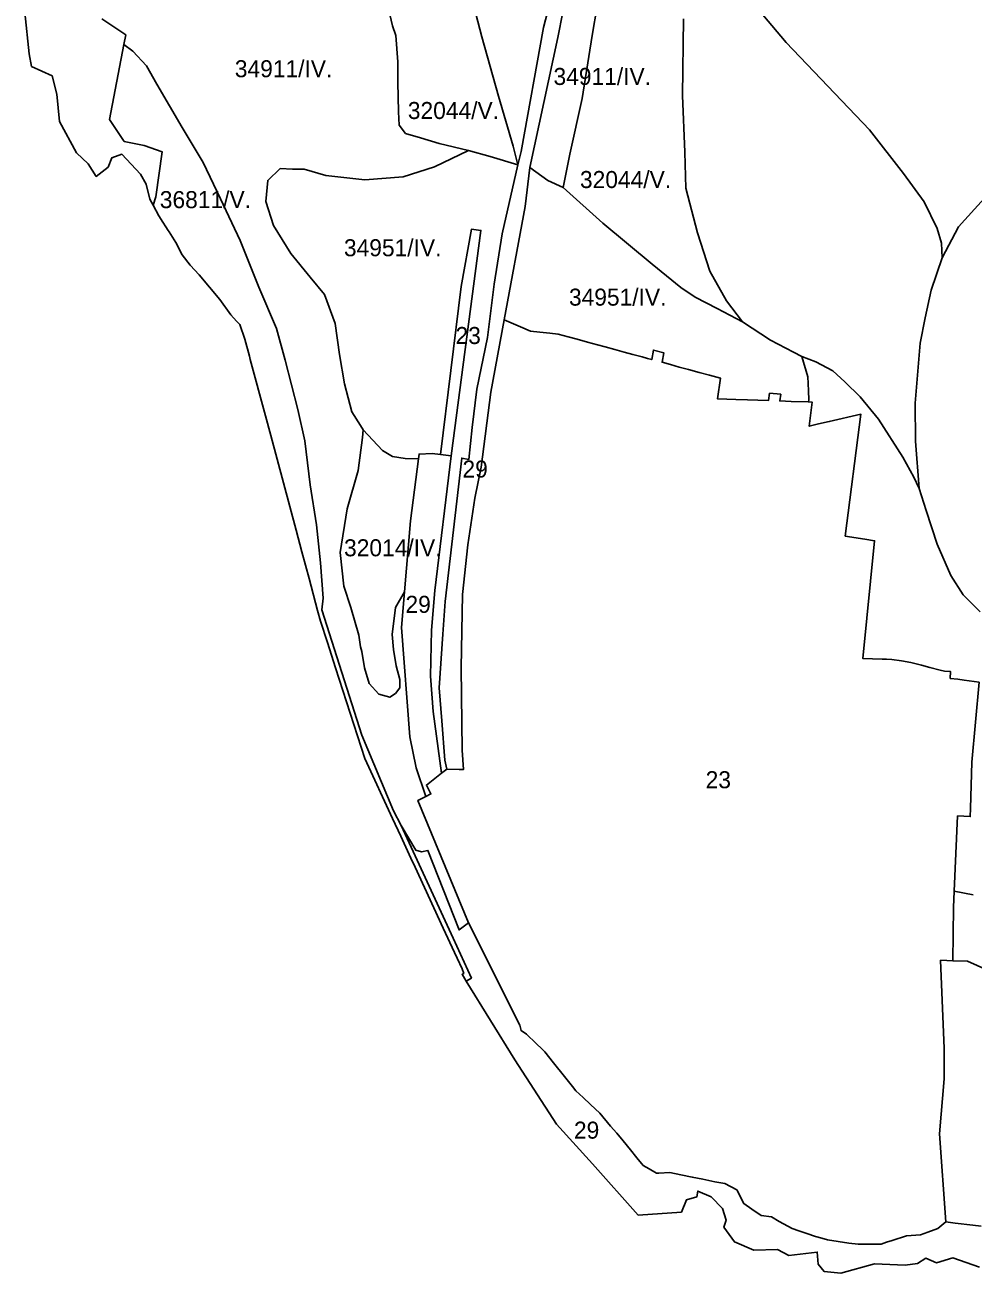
# Model space of a CAD drawing. Extents: x -521621 to -516761, y -1190184 to -1184927.
# Drawn here: x -520918 to -520083, y -1189812 to -1188713 of the extents above; entities that cross this region are included whole.
import ezdxf

# ---------------------------------------------------------------- set-up
doc = ezdxf.new("R2010")
doc.units = 0
doc.layers.add('BPEJ_s', color=7, linetype='Continuous')

msp = doc.modelspace()

# ---------------------------------------------------------------- linework, layer by layer
at = {"layer": 'BPEJ_s'}
for points in [[(-520473.2, -1188838.7), (-520448.5, -1188724), (-520435.4, -1188657), (-520429.1, -1188628.7), (-520418.3, -1188620.7), (-520409.7, -1188617.4), (-520401.2, -1188621.1), (-520400, -1188634.9), (-520404.1, -1188656.5), (-520413.8, -1188696.4), (-520418.3, -1188722.4), (-520427.2, -1188777.8), (-520437.8, -1188827), (-520443.9, -1188856.3), (-520457.3, -1188850.2)], [(-520607.8, -1188676.4), (-520600.9, -1188664.6), (-520588.3, -1188652.8), (-520572, -1188649.6), (-520559, -1188653.2), (-520545.6, -1188660.6), (-520534.6, -1188674.4), (-520520.8, -1188703.3), (-520515.5, -1188723.6), (-520500.8, -1188775.7), (-520487.8, -1188819.7), (-520483.6, -1188836.2), (-520508.2, -1188829), (-520527.2, -1188823.5), (-520552.9, -1188817.6), (-520569.6, -1188812.4), (-520582.6, -1188808.7), (-520588.3, -1188801.4), (-520588.7, -1188789.6), (-520589.5, -1188763.5), (-520589.5, -1188745.6), (-520591.1, -1188722.4), (-520594, -1188713.9), (-520598, -1188697.6)], [(-520830.7, -1188730.3), (-520822.7, -1188736.2), (-520810.7, -1188749.2), (-520801.6, -1188765.2), (-520779.3, -1188803.3), (-520760.8, -1188834.2), (-520745.5, -1188866.3), (-520728.3, -1188903), (-520711.8, -1188944.1), (-520696.2, -1188980.4), (-520688.6, -1189008.3), (-520677.6, -1189051.7), (-520671.3, -1189079.4), (-520666.7, -1189118.2), (-520661, -1189153.4), (-520657.4, -1189187), (-520655.1, -1189217.9), (-520656.3, -1189228.2), (-520621.2, -1189338.8), (-520593.3, -1189405.2), (-520586.4, -1189418.3), (-520540.6, -1189517.5), (-520524.6, -1189552.7), (-520529.2, -1189555.3), (-520532.9, -1189549.3), (-520531.4, -1189548.5), (-520532.9, -1189544.5), (-520537.2, -1189535.1), (-520539.6, -1189530), (-520549.4, -1189508.6), (-520574.3, -1189454.8), (-520577.9, -1189447), (-520586.9, -1189427.6), (-520594, -1189412.2), (-520618.6, -1189359.1), (-520644.3, -1189279.4), (-520651.5, -1189257), (-520657.6, -1189238.1), (-520660.1, -1189228.9), (-520667.6, -1189200.8), (-520673.9, -1189177.3), (-520679, -1189158.2), (-520701.4, -1189074.8), (-520706.1, -1189057.4), (-520719.4, -1189007.8), (-520720.2, -1189004.9), (-520724.2, -1188989.9), (-520728.7, -1188977), (-520731.5, -1188973.9), (-520736.5, -1188968.4), (-520746.1, -1188955), (-520764.3, -1188933.2), (-520772.4, -1188924.5), (-520779.3, -1188915.6), (-520784.9, -1188904.7), (-520790.9, -1188895.2), (-520791.6, -1188894.1), (-520793.7, -1188890.8), (-520796.3, -1188886.8), (-520800, -1188881.2), (-520804.9, -1188871.9), (-520802.6, -1188864.5), (-520796.9, -1188824.9), (-520813, -1188819.2), (-520830.4, -1188815.8), (-520843.5, -1188796.4)], [(-520620, -1189069.8), (-520622.2, -1189066), (-520629.8, -1189053.9), (-520636.4, -1189029.2), (-520640.8, -1189003.4), (-520644.7, -1188975.9), (-520654, -1188950.6), (-520666.6, -1188935.2), (-520683.7, -1188914.3), (-520699, -1188889.6), (-520705.6, -1188868.7), (-520704, -1188850), (-520693, -1188839.6), (-520682.2, -1188840), (-520672, -1188840), (-520652.9, -1188845.7), (-520618.4, -1188849.4), (-520584.6, -1188846.9), (-520557, -1188838), (-520527.2, -1188823.5), (-520508.2, -1188829), (-520483.6, -1188836.2), (-520497.6, -1188897.1), (-520504.7, -1188941.3), (-520510.4, -1188988.4), (-520519.7, -1189034), (-520523.9, -1189067.5), (-520526.8, -1189095.7), (-520533.1, -1189094.6), (-520547.8, -1189220.8), (-520549.8, -1189249.8), (-520553, -1189297), (-520550.8, -1189325.9), (-520548.1, -1189360.8), (-520546.2, -1189368.6), (-520550.9, -1189372.2), (-520558.4, -1189317.9), (-520560.8, -1189286.7), (-520559.8, -1189246.2), (-520556.8, -1189211.3), (-520542.5, -1189092.7), (-520516.3, -1188894.1), (-520524.5, -1188892.8), (-520533.5, -1188943.4), (-520551.8, -1189091.5), (-520559.2, -1189090.4), (-520570.7, -1189091), (-520571.2, -1189095.1), (-520583.1, -1189094.9), (-520594.2, -1189093.1), (-520602.9, -1189088)], [(-520495.9, -1188972.7), (-520477.3, -1188873), (-520473.2, -1188838.7), (-520457.3, -1188850.2), (-520443.9, -1188856.3), (-520408.9, -1188887.6), (-520365.4, -1188923.9), (-520340.2, -1188944.2), (-520327.6, -1188952.7), (-520308.1, -1188962.9), (-520285.7, -1188974.7), (-520261.3, -1188990.6), (-520241, -1189001.2), (-520233.7, -1189005.2), (-520228.4, -1189023), (-520228, -1189028.9), (-520227.6, -1189035.4), (-520227.5, -1189043.4), (-520227.8, -1189045.1), (-520243.1, -1189044.6), (-520253, -1189044.2), (-520252.2, -1189038.4), (-520262, -1189037.4), (-520263, -1189043.9), (-520272.4, -1189043.6), (-520281.5, -1189043.2), (-520291.6, -1189042.9), (-520299.5, -1189042.6), (-520308, -1189042.3), (-520305.2, -1189024.2), (-520314.8, -1189021.6), (-520324.1, -1189019.1), (-520333.4, -1189016.6), (-520341.5, -1189014.4), (-520349.3, -1189012.2), (-520356.7, -1189010.2), (-520355.2, -1189001.8), (-520364.3, -1188999.5), (-520365.8, -1189007.8), (-520369.5, -1189006.8), (-520374.2, -1189005.5), (-520382.4, -1189003.3), (-520390.2, -1189001.2), (-520398.2, -1188999), (-520406.9, -1188996.6), (-520413.7, -1188994.8), (-520422.5, -1188992.4), (-520431.5, -1188989.9), (-520439.3, -1188987.8), (-520448.2, -1188985.4), (-520455.6, -1188984.6), (-520464.4, -1188983.7), (-520472.6, -1188982.8), (-520481.5, -1188979)], [(-520551.8, -1189091.5), (-520533.5, -1188943.4), (-520524.5, -1188892.8), (-520516.3, -1188894.1), (-520542.5, -1189092.7)], [(-520564.7, -1189392.6), (-520560.3, -1189390.4), (-520564.3, -1189382.7), (-520550.9, -1189372.2), (-520546.2, -1189368.6), (-520535.5, -1189369), (-520531.5, -1189368.9), (-520532.9, -1189351.9), (-520533.7, -1189279.4), (-520532.4, -1189214.7), (-520527.8, -1189170.9), (-520521.6, -1189129.9), (-520515.9, -1189102.5), (-520507.6, -1189036.4), (-520495.9, -1188972.7), (-520481.5, -1188979), (-520472.6, -1188982.8), (-520464.4, -1188983.7), (-520455.6, -1188984.6), (-520448.2, -1188985.4), (-520439.3, -1188987.8), (-520431.5, -1188989.9), (-520422.5, -1188992.4), (-520413.7, -1188994.8), (-520406.9, -1188996.6), (-520398.2, -1188999), (-520390.2, -1189001.2), (-520382.4, -1189003.3), (-520374.2, -1189005.5), (-520369.5, -1189006.8), (-520365.8, -1189007.8), (-520364.3, -1188999.5), (-520355.2, -1189001.8), (-520356.7, -1189010.2), (-520349.3, -1189012.2), (-520341.5, -1189014.4), (-520333.4, -1189016.6), (-520324.1, -1189019.1), (-520314.8, -1189021.6), (-520305.2, -1189024.2), (-520308, -1189042.3), (-520299.5, -1189042.6), (-520291.6, -1189042.9), (-520281.5, -1189043.2), (-520272.4, -1189043.6), (-520263, -1189043.9), (-520262, -1189037.4), (-520252.2, -1189038.4), (-520253, -1189044.2), (-520243.1, -1189044.6), (-520227.8, -1189045.1), (-520224.6, -1189045.2), (-520227, -1189066.5), (-520218.8, -1189064.5), (-520209.5, -1189062.4), (-520181.6, -1189055.9), (-520195.4, -1189163.3), (-520178.2, -1189166), (-520169.5, -1189167.4), (-520179.9, -1189271), (-520171.4, -1189271.4), (-520162.9, -1189271.7), (-520159, -1189271.8), (-520154.4, -1189272.1), (-520145.9, -1189273.3), (-520137.6, -1189274.6), (-520128.2, -1189277.1), (-520120.9, -1189279), (-520111.8, -1189281.4), (-520107.9, -1189282.4), (-520102.5, -1189282.6), (-520102.8, -1189288.6), (-520096.1, -1189289.4), (-520090.6, -1189290.1), (-520077.5, -1189292), (-520083.9, -1189362.4), (-520084.9, -1189403.4), (-520085.2, -1189410.4), (-520096.4, -1189409.8), (-520099.3, -1189476.2), (-520100, -1189490.6), (-520100.5, -1189537.4), (-520105.8, -1189537.2), (-520111.3, -1189536.9), (-520108.1, -1189614.6), (-520108.1, -1189641.3), (-520112.3, -1189689.9), (-520106.7, -1189767.4), (-520113.8, -1189773.2), (-520122.7, -1189776.5), (-520129, -1189778.9), (-520141.4, -1189779.8), (-520154, -1189783.8), (-520158.9, -1189785.4), (-520163.6, -1189786.9), (-520174.3, -1189786.9), (-520184.1, -1189786.9), (-520192.2, -1189786.1), (-520210.9, -1189783.1), (-520216, -1189781.8), (-520221.6, -1189780.3), (-520229.1, -1189777.7), (-520236.1, -1189775.3), (-520242, -1189773.3), (-520253.5, -1189767.1), (-520260.4, -1189763), (-520269.5, -1189761.7), (-520277.7, -1189756.3), (-520284.6, -1189751.3), (-520290.7, -1189739.2), (-520301.5, -1189733.7), (-520310.2, -1189732), (-520320.7, -1189729.8), (-520330.1, -1189727.9), (-520340.3, -1189725.9), (-520349.7, -1189724), (-520359.4, -1189724.4), (-520361.6, -1189724.5), (-520368.1, -1189720.7), (-520373.3, -1189717.7), (-520378.8, -1189711), (-520384.5, -1189703.9), (-520390.9, -1189696), (-520396.6, -1189689.3), (-520402, -1189683), (-520411.5, -1189671.7), (-520419.8, -1189663.9), (-520426.3, -1189657.7), (-520432.5, -1189651.9), (-520435.6, -1189648), (-520442.7, -1189639.2), (-520452.3, -1189627.3), (-520460, -1189617.7), (-520470, -1189607.8), (-520473.6, -1189604.3), (-520476.1, -1189601.9), (-520480.9, -1189598.9), (-520482.1, -1189594.1), (-520527.1, -1189503.9), (-520571.7, -1189396.1)], [(-520620, -1189069.8), (-520602.9, -1189088), (-520594.2, -1189093.1), (-520583.1, -1189094.9), (-520571.2, -1189095.1), (-520578.4, -1189149.9), (-520583.5, -1189212.4), (-520591.5, -1189226.1), (-520594.3, -1189250.1), (-520593.3, -1189263.1), (-520591, -1189277.5), (-520587.8, -1189289.5), (-520587.8, -1189296.9), (-520591.5, -1189302), (-520596.6, -1189305.3), (-520606.3, -1189302.5), (-520614.6, -1189293.2), (-520618.8, -1189279.3), (-520621.1, -1189265), (-520622.2, -1189260.8), (-520623.9, -1189250.5), (-520630.8, -1189226.2), (-520637.1, -1189207.3), (-520640.1, -1189177.7), (-520634.1, -1189139.2), (-520624.5, -1189105.6), (-520620.5, -1189076.4)], [(-520583.5, -1189212.4), (-520578.4, -1189149.9), (-520571.2, -1189095.1), (-520570.7, -1189091), (-520559.2, -1189090.4), (-520551.8, -1189091.5), (-520542.5, -1189092.7), (-520556.8, -1189211.3), (-520559.8, -1189246.2), (-520560.8, -1189286.7), (-520558.4, -1189317.9), (-520550.9, -1189372.2), (-520564.3, -1189382.7), (-520560.3, -1189390.4), (-520564.7, -1189392.6), (-520573.3, -1189367.3), (-520579, -1189340.2), (-520586.1, -1189243.8)]]:
    msp.add_lwpolyline(points, close=True, dxfattribs=at)
for points in [[(-520435.4, -1188657), (-520448.5, -1188724), (-520473.2, -1188838.7), (-520477.3, -1188873), (-520495.9, -1188972.7), (-520507.6, -1189036.4), (-520515.9, -1189102.5), (-520521.6, -1189129.9), (-520527.8, -1189170.9), (-520532.4, -1189214.7), (-520533.7, -1189279.4), (-520532.9, -1189351.9), (-520531.5, -1189368.9), (-520535.5, -1189369), (-520546.2, -1189368.6), (-520548.1, -1189360.8), (-520550.8, -1189325.9), (-520553, -1189297), (-520549.8, -1189249.8), (-520547.8, -1189220.8), (-520533.1, -1189094.6), (-520526.8, -1189095.7), (-520523.9, -1189067.5), (-520519.7, -1189034), (-520510.4, -1188988.4), (-520504.7, -1188941.3), (-520497.6, -1188897.1), (-520483.6, -1188836.2), (-520480.9, -1188824.4), (-520461.1, -1188715.4), (-520443, -1188645)], [(-520443, -1188645), (-520461.1, -1188715.4), (-520480.9, -1188824.4), (-520483.6, -1188836.2), (-520487.8, -1188819.7), (-520500.8, -1188775.7), (-520515.5, -1188723.6), (-520520.8, -1188703.3)], [(-520304.4, -1188660.6), (-520247.4, -1188728.4), (-520174.1, -1188805.5), (-520143.9, -1188844), (-520125.8, -1188869), (-520114.5, -1188892.4), (-520110.7, -1188905.3), (-520109.9, -1188918.1), (-520119.7, -1188946.8), (-520125, -1188971), (-520129.2, -1188993.3), (-520133.7, -1189046.2), (-520133.5, -1189079.7), (-520130.3, -1189121.4), (-520134.8, -1189111.3), (-520144.5, -1189093.7), (-520165.9, -1189060.4), (-520182.1, -1189040.6), (-520195.6, -1189027.3), (-520206.2, -1189017.8), (-520221.1, -1189009.7), (-520233.7, -1189005.2), (-520241, -1189001.2), (-520261.3, -1188990.6), (-520285.7, -1188974.7), (-520299.9, -1188956), (-520314.6, -1188930), (-520325.6, -1188896.2), (-520335.7, -1188856.7), (-520336.5, -1188825), (-520338.6, -1188775.3), (-520337.8, -1188707.8)], [(-520072.9, -1188866), (-520095.6, -1188890.9), (-520109.9, -1188918.1), (-520110.7, -1188905.3), (-520114.5, -1188892.4), (-520125.8, -1188869), (-520143.9, -1188844), (-520174.1, -1188805.5), (-520247.4, -1188728.4), (-520304.4, -1188660.6)], [(-520598, -1188697.6), (-520594, -1188713.9), (-520591.1, -1188722.4), (-520589.5, -1188745.6), (-520589.5, -1188763.5), (-520588.7, -1188789.6), (-520588.3, -1188801.4), (-520582.6, -1188808.7), (-520569.6, -1188812.4), (-520552.9, -1188817.6), (-520527.2, -1188823.5), (-520557, -1188838), (-520584.6, -1188846.9), (-520618.4, -1188849.4), (-520652.9, -1188845.7), (-520672, -1188840), (-520682.2, -1188840), (-520693, -1188839.6), (-520704, -1188850), (-520705.6, -1188868.7), (-520699, -1188889.6), (-520683.7, -1188914.3), (-520666.6, -1188935.2), (-520654, -1188950.6), (-520644.7, -1188975.9), (-520640.8, -1189003.4), (-520636.4, -1189029.2), (-520629.8, -1189053.9), (-520622.2, -1189066), (-520620, -1189069.8), (-520620.5, -1189076.4), (-520624.5, -1189105.6), (-520634.1, -1189139.2), (-520640.1, -1189177.7), (-520637.1, -1189207.3), (-520630.8, -1189226.2), (-520623.9, -1189250.5), (-520622.2, -1189260.8), (-520621.1, -1189265), (-520618.8, -1189279.3), (-520614.6, -1189293.2), (-520606.3, -1189302.5), (-520596.6, -1189305.3), (-520591.5, -1189302), (-520587.8, -1189296.9), (-520587.8, -1189289.5), (-520591, -1189277.5), (-520593.3, -1189263.1), (-520594.3, -1189250.1), (-520591.5, -1189226.1), (-520583.5, -1189212.4), (-520586.1, -1189243.8), (-520579, -1189340.2), (-520573.3, -1189367.3), (-520564.7, -1189392.6), (-520571.7, -1189396.1), (-520527.1, -1189503.9), (-520535.5, -1189510.2), (-520562.9, -1189440.2), (-520568.7, -1189441.4), (-520573.6, -1189439.9), (-520586.4, -1189418.3), (-520593.3, -1189405.2), (-520621.2, -1189338.8), (-520656.3, -1189228.2), (-520655.1, -1189217.9), (-520657.4, -1189187), (-520661, -1189153.4), (-520666.7, -1189118.2), (-520671.3, -1189079.4), (-520677.6, -1189051.7), (-520688.6, -1189008.3), (-520696.2, -1188980.4), (-520711.8, -1188944.1), (-520728.3, -1188903), (-520745.5, -1188866.3), (-520760.8, -1188834.2), (-520779.3, -1188803.3), (-520801.6, -1188765.2), (-520810.7, -1188749.2), (-520822.7, -1188736.2), (-520830.7, -1188730.3), (-520829.1, -1188721.8), (-520850.2, -1188707.6)], [(-520337.8, -1188707.8), (-520338.6, -1188775.3), (-520336.5, -1188825), (-520335.7, -1188856.7), (-520325.6, -1188896.2), (-520314.6, -1188930), (-520299.9, -1188956), (-520285.7, -1188974.7), (-520308.1, -1188962.9), (-520327.6, -1188952.7), (-520340.2, -1188944.2), (-520365.4, -1188923.9), (-520408.9, -1188887.6), (-520443.9, -1188856.3), (-520437.8, -1188827), (-520427.2, -1188777.8), (-520418.3, -1188722.4), (-520413.8, -1188696.4)], [(-520850.2, -1188707.6), (-520829.1, -1188721.8), (-520830.7, -1188730.3), (-520843.5, -1188796.4), (-520830.4, -1188815.8), (-520813, -1188819.2), (-520796.9, -1188824.9), (-520802.6, -1188864.5), (-520804.9, -1188871.9), (-520807.9, -1188866.5), (-520811.1, -1188853.4), (-520816.1, -1188844.5), (-520832.4, -1188827), (-520841.3, -1188830), (-520844.7, -1188838.2), (-520855, -1188846.4), (-520862.2, -1188835.3), (-520872.4, -1188825.7), (-520887.5, -1188798.2), (-520889.7, -1188774.1), (-520893.8, -1188757.9), (-520912.1, -1188749.6), (-520914.1, -1188738.4), (-520917.9, -1188702.1)], [(-520076.6, -1189230.1), (-520091.5, -1189215), (-520102.4, -1189198), (-520114.3, -1189170.3), (-520124.2, -1189140.8), (-520130.3, -1189121.4), (-520133.5, -1189079.7), (-520133.7, -1189046.2), (-520129.2, -1188993.3), (-520125, -1188971), (-520119.7, -1188946.8), (-520109.9, -1188918.1), (-520095.6, -1188890.9), (-520072.9, -1188866)], [(-520082.7, -1189479.4), (-520099.3, -1189476.2), (-520096.4, -1189409.8), (-520085.2, -1189410.4), (-520084.9, -1189403.4), (-520083.9, -1189362.4), (-520077.5, -1189292), (-520090.6, -1189290.1), (-520096.1, -1189289.4), (-520102.8, -1189288.6), (-520102.5, -1189282.6), (-520107.9, -1189282.4), (-520111.8, -1189281.4), (-520120.9, -1189279), (-520128.2, -1189277.1), (-520137.6, -1189274.6), (-520145.9, -1189273.3), (-520154.4, -1189272.1), (-520159, -1189271.8), (-520162.9, -1189271.7), (-520171.4, -1189271.4), (-520179.9, -1189271), (-520169.5, -1189167.4), (-520178.2, -1189166), (-520195.4, -1189163.3), (-520181.6, -1189055.9), (-520209.5, -1189062.4), (-520218.8, -1189064.5), (-520227, -1189066.5), (-520224.6, -1189045.2), (-520227.8, -1189045.1), (-520227.5, -1189043.4), (-520227.6, -1189035.4), (-520228, -1189028.9), (-520228.4, -1189023), (-520233.7, -1189005.2), (-520221.1, -1189009.7), (-520206.2, -1189017.8), (-520195.6, -1189027.3), (-520182.1, -1189040.6), (-520165.9, -1189060.4), (-520144.5, -1189093.7), (-520134.8, -1189111.3), (-520130.3, -1189121.4), (-520124.2, -1189140.8), (-520114.3, -1189170.3), (-520102.4, -1189198), (-520091.5, -1189215), (-520076.6, -1189230.1)], [(-520077, -1189807.4), (-520100.5, -1189799.2), (-520115.1, -1189803.6), (-520124.3, -1189799.5), (-520131.8, -1189804), (-520142.6, -1189805.5), (-520169.5, -1189804.4), (-520199.2, -1189812.5), (-520214, -1189811.1), (-520219.2, -1189804.5), (-520220, -1189794), (-520245.1, -1189797), (-520255.1, -1189791.7), (-520276, -1189792.3), (-520293, -1189784.9), (-520302.4, -1189772.1), (-520300.1, -1189765.8), (-520303.5, -1189755.5), (-520313.4, -1189745.4), (-520325.2, -1189740.3), (-520326.1, -1189745.4), (-520335.3, -1189748.1), (-520339.6, -1189758.7), (-520377.6, -1189761.5), (-520418.1, -1189716.4), (-520449.7, -1189681.2), (-520486.3, -1189624.6), (-520529.2, -1189555.3), (-520524.6, -1189552.7), (-520540.6, -1189517.5), (-520586.4, -1189418.3), (-520573.6, -1189439.9), (-520568.7, -1189441.4), (-520562.9, -1189440.2), (-520535.5, -1189510.2), (-520527.1, -1189503.9), (-520482.1, -1189594.1), (-520480.9, -1189598.9), (-520476.1, -1189601.9), (-520473.6, -1189604.3), (-520470, -1189607.8), (-520460, -1189617.7), (-520452.3, -1189627.3), (-520442.7, -1189639.2), (-520435.6, -1189648), (-520432.5, -1189651.9), (-520426.3, -1189657.7), (-520419.8, -1189663.9), (-520411.5, -1189671.7), (-520402, -1189683), (-520396.6, -1189689.3), (-520390.9, -1189696), (-520384.5, -1189703.9), (-520378.8, -1189711), (-520373.3, -1189717.7), (-520368.1, -1189720.7), (-520361.6, -1189724.5), (-520359.4, -1189724.4), (-520349.7, -1189724), (-520340.3, -1189725.9), (-520330.1, -1189727.9), (-520320.7, -1189729.8), (-520310.2, -1189732), (-520301.5, -1189733.7), (-520290.7, -1189739.2), (-520284.6, -1189751.3), (-520277.7, -1189756.3), (-520269.5, -1189761.7), (-520260.4, -1189763), (-520253.5, -1189767.1), (-520242, -1189773.3), (-520236.1, -1189775.3), (-520229.1, -1189777.7), (-520221.6, -1189780.3), (-520216, -1189781.8), (-520210.9, -1189783.1), (-520192.2, -1189786.1), (-520184.1, -1189786.9), (-520174.3, -1189786.9), (-520163.6, -1189786.9), (-520158.9, -1189785.4), (-520154, -1189783.8), (-520141.4, -1189779.8), (-520129, -1189778.9), (-520122.7, -1189776.5), (-520113.8, -1189773.2), (-520106.7, -1189767.4), (-520098.6, -1189768.4), (-520093.1, -1189769.1), (-520088.3, -1189769.7), (-520083.1, -1189770.3), (-520075.6, -1189771.2)], [(-520059.4, -1189550.3), (-520087.7, -1189537.8), (-520100.5, -1189537.4), (-520100, -1189490.6), (-520099.3, -1189476.2), (-520082.7, -1189479.4)], [(-520075.6, -1189771.2), (-520083.1, -1189770.3), (-520088.3, -1189769.7), (-520093.1, -1189769.1), (-520098.6, -1189768.4), (-520106.7, -1189767.4), (-520112.3, -1189689.9), (-520108.1, -1189641.3), (-520108.1, -1189614.6), (-520111.3, -1189536.9), (-520105.8, -1189537.2), (-520100.5, -1189537.4), (-520087.7, -1189537.8), (-520059.4, -1189550.3)]]:
    msp.add_lwpolyline(points, dxfattribs=at)

# ---------------------------------------------------------------- texts
for s, p in [('34911/IV.', (-520733, -1188759.1)), ('34911/IV.', (-520452.3, -1188765.9)), ('32044/V.', (-520580.6, -1188795.9)), ('32044/V.', (-520429, -1188856.7)), ('36811/V.', (-520799.1, -1188874.4)), ('34951/IV.', (-520636.9, -1188916.8)), ('34951/IV.', (-520438.7, -1188960.3)), ('23', (-520538.6, -1188994.1)), ('29', (-520532.5, -1189111.7)), ('32014/IV.', (-520636.8, -1189181.1)), ('29', (-520582.7, -1189230.9)), ('23', (-520318.3, -1189385.4)), ('29', (-520434.3, -1189694.1))]:
    msp.add_text(s, height=15, dxfattribs=at).set_placement(p)

doc.saveas('drawing.dxf')
